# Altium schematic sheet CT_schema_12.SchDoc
size 274 x 160 mm
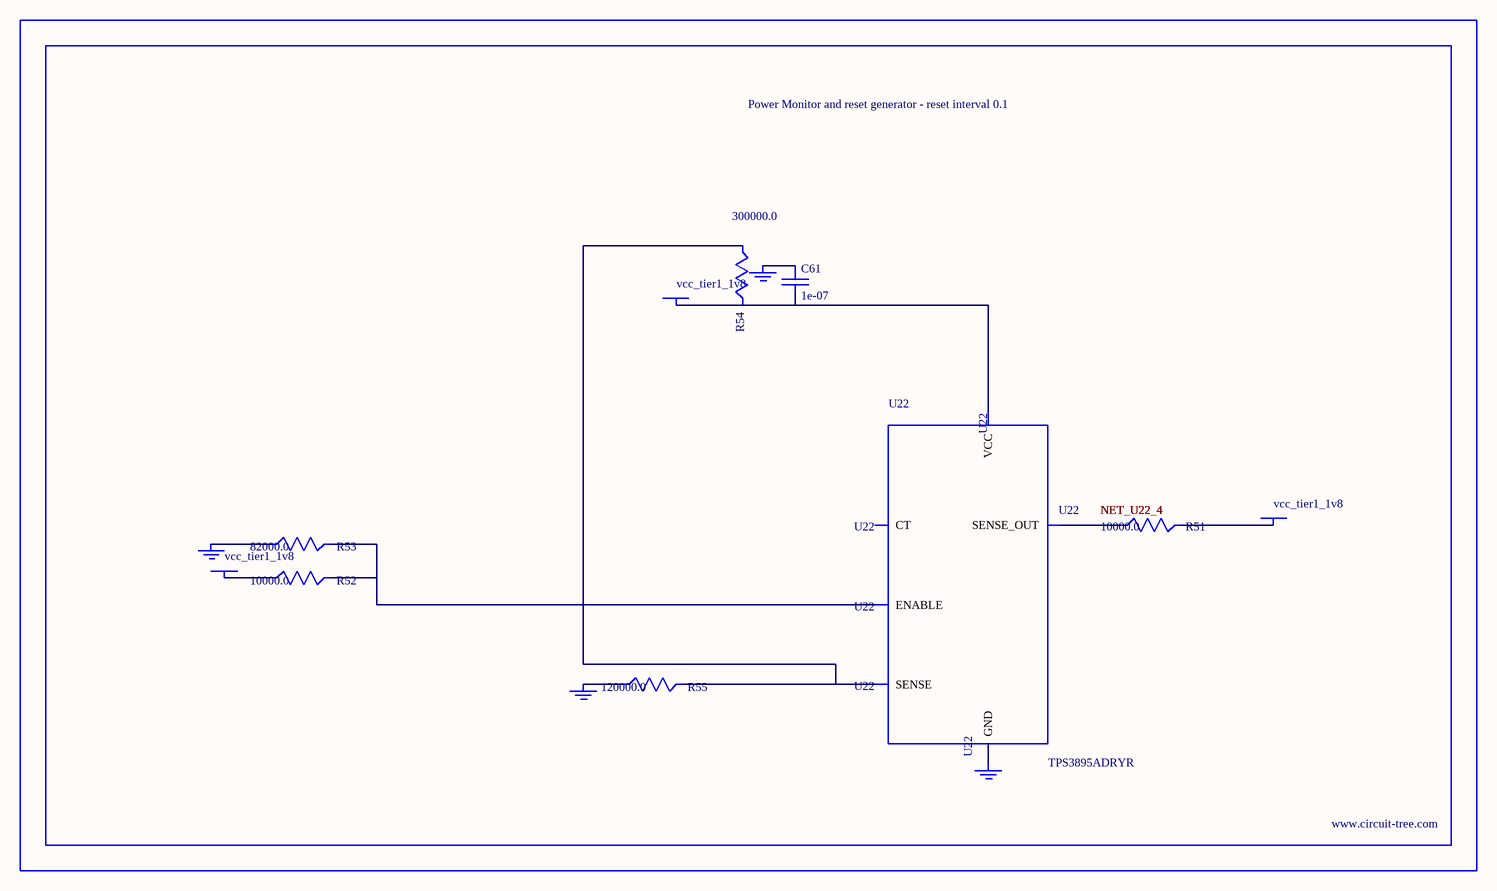
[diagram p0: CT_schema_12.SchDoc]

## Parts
BORDER11  (no value)
C61  1e-07  [C0402]
GND_INSTANCE_11_0  (no value)
GND_INSTANCE_11_1  (no value)
GND_INSTANCE_11_2  (no value)
GND_INSTANCE_11_3  (no value)
POWER_INSTANCE_11_0  vcc_tier1_1v8
POWER_INSTANCE_11_1  vcc_tier1_1v8
POWER_INSTANCE_11_2  vcc_tier1_1v8
R51  10000.0  [R0603]
R52  10000.0  [R0603]
R53  82000.0  [R0603]
R54  300000.0  [R0603]
R55  120000.0  [R0603]
U22  TPS3895ADRYR  [SON-6]

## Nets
NetC61_1: C61.1 GND_INSTANCE_11_2.0(GND)
NetC61_2: C61.2 POWER_INSTANCE_11_2.0(PWR) R54.2 U22.6(VCC)
NetGND_INSTANCE_11_0_0: GND_INSTANCE_11_0.0(GND) R53.1
NetGND_INSTANCE_11_1_0: GND_INSTANCE_11_1.0(GND) R55.1
NetGND_INSTANCE_11_3_0: GND_INSTANCE_11_3.0(GND) U22.2(GND)
NetPOWER_INSTANCE_11_0_0: POWER_INSTANCE_11_0.0(PWR) R52.1
NetPOWER_INSTANCE_11_1_0: POWER_INSTANCE_11_1.0(PWR) R51.2
NetR51_1: R51.1 U22.4(SENSE_OUT)
NetR52_2: R52.2 R53.2 U22.1(ENABLE)
NetR54_1: R54.1 R55.2 U22.3(SENSE)

Not connected (* = marked no-connect by the designer): U22 5(CT)

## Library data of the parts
BORDER11 = BORDER_PAGE11
C61 = C0402C104K3RACTU
GND_INSTANCE_11_0-GND_INSTANCE_11_3 = GND
POWER_INSTANCE_11_0-POWER_INSTANCE_11_2 = PWR
R51 R52 = RC0603JR-0710KL
R53 = RC0603JR-0782KL
R54 = RC0603JR-07300KL
R55 = RC0603JR-07120KL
